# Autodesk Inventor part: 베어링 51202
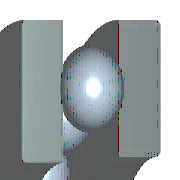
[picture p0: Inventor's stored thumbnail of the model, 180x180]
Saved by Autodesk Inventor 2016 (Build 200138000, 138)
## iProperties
Created: 2012-02
Part Number: 베어링 51202
Material: 강철, 연강
Description: 롤링 베어링 - 플랫 뒷면이 있는 스러스트 볼 베어링
Document SubType Name: Modeling
Standard: KS B 2022
Designer: mduedu
Standards Organization: KS
Language: ko-KR
Size Designation: 51202 - 15 x 32 x 12
Categories: <MemberInstance><Categories><Category DisplayName="샤프트 부품" InternalName="7f7aeb1f-a693-4053-b835-cee3144e0d98" Mnemonic="SHFT"><Category DisplayName="베어링" Inter
Density: 7.85 g/cm^3
Appearance: 진녹색
Mass: 37.6706 g
Surface Area: 40.414 cm^2
Volume: 4.7988 cm^3
IsCustomPart: 1
Author: mduedu
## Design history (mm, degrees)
sketch "스케치1" dims "d3" = 5.28 (= 0.44 x KB)
  geometry: L1 (6, 9.61)-(6, 14.89); L2 (8.64, 12.25)-(3.36, 12.25); L3 (3.6, 16)-(0, 16); L4 (3.6, 7.5)-(0, 7.5); L5 (8.4, 13.35)-(8.4, 16); L6 (8.4, 16)-(12, 16); L7 (12, 16)-(12, 8.5); L8 (12, 8.5)-(8.4, 8.5); L9 (8.4, 8.5)-(8.4, 11.15); L10 (3.6, 16)-(3.6, 13.35); L11 (3.6, 11.15)-(3.6, 7.5); L12 (-1.8, 0)-(10.8, 0) reference; L13 (0, -0.022)-(0, 5.522) reference; 1 further point
  constraints: 22 end point, 5 perpendicular, 2 equal length, 2 midpoint, 2 parallel, 2 point on line, 1 collinear, 10 other
  dimensions: "d8" = 4.8 diameter of L11 L1 (= 0.4 x KB); "d11" = 15 diameter of L4 L12 (= WD); "d12" = 17 diameter of L8 L12 (= KAD1); "d13" = 32 diameter of L3 L12 (= KID1); "d14" = 32 diameter of L6 L12 (= BD); "d15" = 24.5 diameter of point (6, 12.25) L12 (= 0.5 x KID1 + 0.5 x KAD1); "d16" = 6 distance from line of point (6, 12.25) L13 (= 0.5 x KB); "d18" = 12 distance between parallel lines of L7 L13 (= KB)
revolve "본체" stored, may be unused: angle "d9" = 90 deg
revolve "볼" stored, may be unused: angle "d10" = 90 deg
pattern_circular "IDS_ARRAYBALL[SIMPL:T]" dims angle "d2" = 360 deg
body "Solid1"
fillet "모깎기1" dims "d4" = 0.6 (= KRS)
fillet "모깎기2" dims "d5" = 0.6 (= KRS)
other parameters: "WD" = 15 [user parameter; used in 2 equation terms], "KAD1" = 17 [user parameter; used in 3 equation terms], "KID1" = 32 [user parameter; used in 3 equation terms], "BD" = 32 [user parameter; used in 2 equation terms], "KB" = 12 [user parameter; used in 6 equation terms], "KRS" = 0.6 [user parameter; used in 2 equation terms], "d0" = 2.4 (= 0.2 x KB), "d6" = 0, "d7" = 0, "d19" = 0, "d41" = 0, "d42" = 0, "WR" = 7.5 (= 0.5 x WD) [user parameter], "BC" = 1.65e+07 [user parameter], "BBA" = 90 deg [user parameter], "BC0" = 2.7e+07 [user parameter], "BR" = 16 (= 0.5 x BD) [user parameter]
